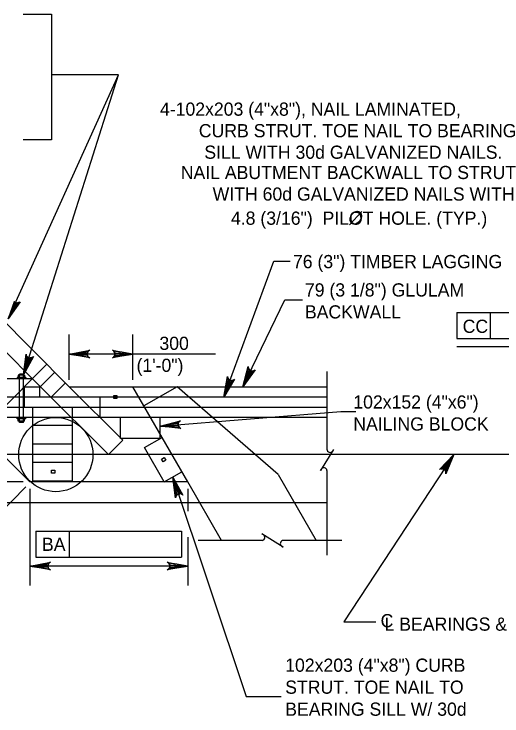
# Model space of a CAD drawing. Extents: x 635440 to 640306, y 296653 to 298484.
# Drawn here: x 638999.2 to 639110.1, y 298096.3 to 298255.9 of the extents above; entities that cross this region are included whole.
import ezdxf

# ---------------------------------------------------------------- set-up
doc = ezdxf.new("R2010")
doc.units = 0
for name, color, linetype in [('4', 7, 'Continuous'), ('5', 7, 'Continuous'), ('52', 7, 'Continuous')]:
    doc.layers.add(name, color=color, linetype=linetype)

msp = doc.modelspace()

# ---------------------------------------------------------------- linework, layer by layer
at = {"layer": '4'}
for p, q in [((639011.78, 298171.18), (638982.26, 298200.71)), ((639005.21, 298171.18), (638978.97, 298197.42)), ((639002.81, 298149.52), (638966.94, 298185.39)), ((639006.68, 298176.28), (638991.37, 298160.97)), ((639001.62, 298173.78), (639000.17, 298173.78)), ((639000.17, 298173.78), (639000.17, 298173.26)), ((639001.35, 298174.05), (639000.43, 298174.05)), ((639000.43, 298163.07), (639000.43, 298174.05)), ((639001.35, 298163.07), (639001.35, 298174.05)), ((639001.62, 298173.78), (639001.62, 298173.26)), ((639008.49, 298174.46), (639005.17, 298171.14)), ((639003.39, 298172.99), (638996.68, 298172.99)), ((639001.88, 298173.26), (638999.91, 298173.26)), ((638999.91, 298173.26), (638999.91, 298172.99)), ((639001.88, 298173.26), (639001.88, 298172.99)), ((639010.94, 298172.02), (639007.61, 298168.69)), ((639001.58, 298166.53), (639001.58, 298171.18)), ((639001.58, 298171.18), (639005.21, 298171.18)), ((639005.11, 298168.77), (639005.11, 298171.27)), ((639020.65, 298155.73), (639005.21, 298171.18)), ((639011.78, 298171.18), (639026.22, 298171.18)), ((639023.94, 298159.02), (639011.78, 298171.18)), ((639026.22, 298171.18), (639070.36, 298171.18)), ((639038.72, 298149.52), (639026.22, 298171.18)), ((639036.26, 298171.18), (639028.73, 298166.83)), ((639059.24, 298151.2), (639036.26, 298171.18)), ((639070.36, 298168.83), (638988.54, 298168.83)), ((639018.78, 298164.17), (639018.78, 298168.83)), ((638988.54, 298166.53), (639070.36, 298166.53)), ((639003.5, 298149.71), (639003.5, 298166.53)), ((639012.53, 298149.71), (639012.53, 298166.53)), ((639070.36, 298164.17), (638988.54, 298164.17)), ((638999.91, 298163.86), (638999.91, 298164.12)), ((639001.88, 298163.86), (638999.91, 298163.86)), ((639000.17, 298163.33), (639000.17, 298163.86)), ((639001.62, 298163.33), (639001.62, 298163.86)), ((639001.88, 298163.86), (639001.88, 298164.12)), ((639023.42, 298159.36), (639023.42, 298164.17)), ((639032.45, 298159.36), (639032.45, 298164.17)), ((639001.62, 298163.33), (639000.17, 298163.33)), ((639001.35, 298163.07), (639000.43, 298163.07)), ((639012.53, 298162.32), (639003.5, 298162.32)), ((639023.94, 298159.02), (639020.65, 298155.73)), ((639032.45, 298159.36), (639023.42, 298159.36)), ((639028.84, 298157.34), (639032.87, 298159.66)), ((639012.53, 298158.12), (639003.5, 298158.12)), ((639033.36, 298149.52), (639028.84, 298157.34)), ((639195.31, 298155.73), (638975.37, 298155.73)), ((639012.53, 298153.92), (639003.5, 298153.92)), ((639033.36, 298149.52), (639037.38, 298151.85)), ((639059.24, 298151.2), (639067.88, 298136.23)), ((639038.72, 298149.52), (639002.81, 298149.52)), ((639012.53, 298149.71), (639003.5, 298149.71)), ((639046.4, 298136.23), (639038.72, 298149.52)), ((638988.54, 298144.87), (639041.41, 298144.87)), ((639041.41, 298144.87), (639070.36, 298144.87))]:
    msp.add_line(p, q, dxfattribs=at)
for points in [[(638997.85, 298186.6), (639022.97, 298242.05)], [(639051.19, 298171.18), (639060.78, 298190.95), (639064.78, 298190.95)], [(639032.45, 298162.2), (639073.47, 298165.51), (639076.91, 298165.51)]]:
    msp.add_lwpolyline(points, dxfattribs=at)
for points in [[(639022.57, 298168.47), (639021.87, 298168.47), (639021.87, 298169.17), (639022.57, 298169.17)], [(639032.45, 298162.2), (639035.41, 298162.19), (639035.37, 298162.68)], [(639033.1, 298154.12), (639032.76, 298154.72), (639033.36, 298155.07), (639033.71, 298154.47)], [(639008.46, 298151.52), (639007.76, 298151.52), (639007.76, 298152.21), (639008.46, 298152.21)]]:
    msp.add_lwpolyline(points, close=True, dxfattribs=at)
msp.add_circle((639008.71, 298155.74), 8.44, dxfattribs=at)
at = {"layer": '5'}
for p, q in [((639001.28, 298255.9), (639007.76, 298255.9)), ((639007.76, 298255.9), (639007.76, 298227.31)), ((639007.76, 298227.31), (639001.28, 298227.31)), ((639075.46, 298207.95), (639078.26, 298211.01)), ((639058.31, 298199.69), (639061.98, 298199.69)), ((639099.88, 298188.03), (639139.26, 298188.03)), ((639099.88, 298188.03), (639099.88, 298182.13)), ((639107.45, 298188.03), (639107.45, 298182.13)), ((639011.78, 298172.71), (639011.78, 298183.03)), ((639026.22, 298172.71), (639026.22, 298183.03)), ((639099.88, 298182.13), (639139.26, 298182.13)), ((639159.09, 298180.22), (639099.89, 298180.22)), ((639045.01, 298178.6), (639011.78, 298178.6)), ((639070.36, 298174.64), (639070.36, 298156.96)), ((639070.36, 298152.1), (639070.36, 298132.9)), ((639001.27, 298149.52), (638981.37, 298149.52)), ((639001.92, 298148.43), (638980.75, 298126.92)), ((639002.81, 298147.98), (639002.81, 298125.97)), ((639038.72, 298147.99), (639038.72, 298142.85)), ((639004.17, 298138.31), (639037.29, 298138.31)), ((639004.17, 298138.31), (639004.17, 298132.4)), ((639011.73, 298138.31), (639011.73, 298132.4)), ((639037.29, 298138.31), (639037.29, 298132.4)), ((639038.72, 298136.99), (639038.72, 298125.97)), ((639055.59, 298136.23), (639041.06, 298136.23)), ((639073.7, 298136.23), (639060.44, 298136.23)), ((639004.17, 298132.4), (639037.29, 298132.4)), ((639038.72, 298130.4), (639002.81, 298130.4)), ((639051.97, 298100.76), (639059.96, 298100.76))]:
    msp.add_line(p, q, dxfattribs=at)
for points in [[(639001.35, 298173.87), (639022.97, 298242.05), (639007.76, 298242.05)], [(639046.92, 298168.83), (639058.31, 298199.68)], [(638999.16, 298190.63), (638999.26, 298190.48), (638999.39, 298190.39), (638999.52, 298190.31), (638999.68, 298190.26), (638999.83, 298190.22), (639000.01, 298190.24), (639000.19, 298190.26), (639000.38, 298190.38), (639000.57, 298190.49), (638997.85, 298186.6), (639000.38, 298190.38), (639000.19, 298190.26), (638997.85, 298186.6), (639000.01, 298190.24), (638999.83, 298190.22), (638997.85, 298186.6), (638999.68, 298190.26), (638999.52, 298190.31), (638997.85, 298186.6), (638999.39, 298190.39), (638999.26, 298190.48), (638997.85, 298186.6)], [(639001.35, 298173.87), (639001.93, 298178.58), (639001.99, 298178.37), (639002.06, 298178.16), (639002.18, 298178.03), (639002.3, 298177.89), (639002.44, 298177.82), (639002.58, 298177.75), (639002.74, 298177.73), (639002.9, 298177.7), (639003.07, 298177.75), (639003.25, 298177.79), (639003.42, 298177.92), (639003.6, 298178.05), (639001.35, 298173.87), (639003.42, 298177.92), (639003.25, 298177.79), (639001.35, 298173.87), (639003.07, 298177.75), (639002.9, 298177.7), (639001.35, 298173.87), (639002.74, 298177.73), (639002.58, 298177.75), (639001.35, 298173.87), (639002.44, 298177.82), (639002.3, 298177.89), (639001.35, 298173.87), (639002.18, 298178.03), (639002.06, 298178.16), (639001.35, 298173.87), (639001.99, 298178.37)], [(639011.78, 298178.6), (639016.44, 298179.48), (639016.09, 298179.23), (639015.9, 298178.91), (639015.85, 298178.6), (639015.9, 298178.29), (639016.09, 298177.98), (639016.44, 298177.73), (639011.78, 298178.6), (639016.09, 298177.98), (639015.9, 298178.29), (639011.78, 298178.6), (639015.85, 298178.6), (639015.9, 298178.91), (639011.78, 298178.6), (639016.09, 298179.23)], [(639026.22, 298178.6), (639021.56, 298177.73), (639021.92, 298177.98), (639022.11, 298178.29), (639022.16, 298178.6), (639022.11, 298178.91), (639021.92, 298179.23), (639021.56, 298179.48), (639026.22, 298178.6), (639021.92, 298179.23), (639022.11, 298178.91), (639026.22, 298178.6), (639022.16, 298178.6), (639022.11, 298178.29), (639026.22, 298178.6), (639021.92, 298177.98)], [(639046.92, 298168.83), (639047.71, 298173.5), (639047.82, 298173.08), (639048.05, 298172.8), (639048.33, 298172.64), (639048.64, 298172.58), (639049, 298172.65), (639049.35, 298172.9), (639046.92, 298168.83), (639049, 298172.65), (639048.64, 298172.58), (639046.92, 298168.83), (639048.33, 298172.64), (639048.05, 298172.8), (639046.92, 298168.83), (639047.82, 298173.08)], [(639032.45, 298162.2), (639037.02, 298163.45), (639036.69, 298163.17), (639036.52, 298162.84), (639036.5, 298162.53), (639036.57, 298162.22), (639036.79, 298161.92), (639037.16, 298161.7), (639032.45, 298162.2), (639036.79, 298161.92), (639036.57, 298162.22), (639032.45, 298162.2), (639036.5, 298162.53), (639036.52, 298162.84), (639032.45, 298162.2), (639036.69, 298163.17)], [(639071.68, 298156.6), (639071.87, 298156.9), (639068.85, 298152.09), (639069.05, 298152.41)], [(639099.22, 298155.73), (639074.17, 298117.7), (639081.5, 298117.7)], [(639099.22, 298155.73), (639097.39, 298151.36), (639097.38, 298151.8), (639097.22, 298152.12), (639096.99, 298152.34), (639096.7, 298152.47), (639096.33, 298152.49), (639095.93, 298152.32), (639099.22, 298155.73), (639096.33, 298152.49), (639096.7, 298152.47), (639099.22, 298155.73), (639096.99, 298152.34), (639097.22, 298152.12), (639099.22, 298155.73), (639097.38, 298151.8)], [(639035.29, 298150.64), (639051.97, 298100.76)], [(639035.29, 298150.64), (639037.6, 298146.5), (639037.25, 298146.76), (639036.89, 298146.84), (639036.58, 298146.79), (639036.3, 298146.64), (639036.06, 298146.36), (639035.94, 298145.94), (639035.29, 298150.64), (639036.06, 298146.36), (639036.3, 298146.64), (639035.29, 298150.64), (639036.58, 298146.79), (639036.89, 298146.84), (639035.29, 298150.64), (639037.25, 298146.76)], [(639060.09, 298134.9), (639060.39, 298134.71), (639055.58, 298137.74), (639055.9, 298137.54)], [(639002.81, 298130.4), (639007.48, 298131.27), (639007.12, 298131.02), (639006.93, 298130.71), (639006.88, 298130.4), (639006.93, 298130.09), (639007.12, 298129.77), (639007.48, 298129.53), (639002.81, 298130.4), (639007.12, 298129.77), (639006.93, 298130.09), (639002.81, 298130.4), (639006.88, 298130.4), (639006.93, 298130.71), (639002.81, 298130.4), (639007.12, 298131.02)], [(639038.72, 298130.4), (639034.06, 298129.53), (639034.42, 298129.77), (639034.61, 298130.09), (639034.66, 298130.4), (639034.61, 298130.71), (639034.42, 298131.02), (639034.06, 298131.27), (639038.72, 298130.4), (639034.42, 298131.02), (639034.61, 298130.71), (639038.72, 298130.4), (639034.66, 298130.4), (639034.61, 298130.09), (639038.72, 298130.4), (639034.42, 298129.77)]]:
    msp.add_lwpolyline(points, dxfattribs=at)
for points in [[(639014.74, 298179.09), (639014.74, 298178.11), (639011.78, 298178.6)], [(639023.27, 298179.09), (639023.27, 298178.11), (639026.22, 298178.6)], [(639099.22, 298155.73), (639097.39, 298153.41), (639097.8, 298153.13)], [(639035.29, 298150.64), (639035.99, 298147.76), (639036.46, 298147.92)], [(639005.77, 298130.89), (639005.77, 298129.91), (639002.81, 298130.4)], [(639035.77, 298130.89), (639035.77, 298129.91), (639038.72, 298130.4)]]:
    msp.add_lwpolyline(points, close=True, dxfattribs=at)
for centre, start, end in [((639071.07, 298156.96), 180, 330), ((639069.65, 298152.04), 5.3286, 147.8672), ((639055.52, 298136.93), 275.3286, 57.8672), ((639060.44, 298135.52), 90, 240)]:
    msp.add_arc(centre, 0.71, start, end, dxfattribs=at)
msp.add_spline([(639077.97, 298210.71), (639077.76, 298210.88), (639077.54, 298210.94), (639077.26, 298210.97), (639077.11, 298210.97), (639076.84, 298210.91), (639076.59, 298210.79), (639076.42, 298210.7), (639076.09, 298210.43), (639075.83, 298210.09), (639075.67, 298209.78), (639075.58, 298209.49), (639075.55, 298209.22), (639075.58, 298208.99), (639075.69, 298208.66), (639075.81, 298208.49), (639076.05, 298208.31), (639076.41, 298208.22), (639076.83, 298208.23), (639077.35, 298208.47), (639077.73, 298208.8), (639078.02, 298209.19), (639078.21, 298209.61), (639078.27, 298210.07), (639078.19, 298210.36), (639077.99, 298210.71)], degree=3, dxfattribs=at)
at = {"layer": '52'}
msp.add_lwpolyline([(639051.19, 298171.18), (639052.44, 298175.75), (639052.51, 298175.32), (639052.71, 298175.02), (639052.97, 298174.83), (639053.27, 298174.74), (639053.63, 298174.77), (639054.01, 298174.99), (639051.19, 298171.18), (639053.63, 298174.77), (639053.27, 298174.74), (639051.19, 298171.18), (639052.97, 298174.83), (639052.71, 298175.02), (639051.19, 298171.18), (639052.51, 298175.32)], dxfattribs=at)

# ---------------------------------------------------------------- texts
at = {"layer": '5'}
for s, height, p in [('4-102x203 (4"x8"), NAIL LAMINATED,', 3.0001, (639032.38, 298232.78)), ('CURB STRUT. TOE NAIL TO BEARING', 3.0001, (639041.22, 298227.88)), ('SILL WITH 30d GALVANIZED NAILS.', 3.0001, (639042.47, 298222.99)), ('NAIL ABUTMENT BACKWALL TO STRUT ', 3.0001, (639037.11, 298218.38)), ('WITH 60d GALVANIZED NAILS WITH', 3.0001, (639044.36, 298213.48)), ('4.8 (3/16")  PILOT HOLE. (TYP.)', 3.0001, (639048.52, 298207.99)), ('76 (3") TIMBER LAGGING', 3.0001, (639062.62, 298198.12)), ('79 (3 1/8") GLULAM', 3.0001, (639065.34, 298191.68)), ('BACKWALL', 3, (639065.34, 298186.68)), ('CC', 3, (639101.2, 298183.41)), ('300', 3, (639032.26, 298179.54)), ('(1\'-0")', 3, (639027.06, 298174.54)), ('102x152 (4"x6")', 3.0001, (639076.34, 298166.2)), ('NAILING BLOCK', 3.0001, (639076.34, 298161.2)), ('C', 3, (639082.54, 298116.48)), ('L BEARINGS & BEARING SILL', 3.0001, (639083.44, 298115.7)), ('102x203 (4"x8") CURB', 3.0001, (639060.86, 298106.36)), ('STRUT. TOE NAIL TO', 3.0001, (639060.86, 298101.36)), ('BEARING SILL W/ 30d', 3.0001, (639060.86, 298096.36))]:
    msp.add_text(s, height=height, dxfattribs=at).set_placement(p)
msp.add_text('BA', height=3, rotation=359.9382, dxfattribs=at).set_placement((639005.56, 298133.85))

doc.saveas('drawing.dxf')
